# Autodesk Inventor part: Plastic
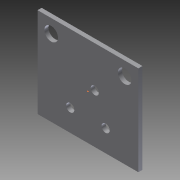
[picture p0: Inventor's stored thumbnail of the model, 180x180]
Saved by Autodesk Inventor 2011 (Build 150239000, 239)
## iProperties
Created: 2014-06
Part Number: Plastic
Document SubType Name: Modeling
Designer: Evgeny
Density: 1 g/cm^3
Author: Evgeny
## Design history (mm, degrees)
sketch "Эскиз1"
  geometry: 1 further point
sketch "Эскиз2"
  geometry: L1 (-18.5, -16.5)-(18.5, -16.5); L2 (18.5, -16.5)-(18.5, 16.5); L3 (18.5, 16.5)-(-18.5, 16.5); L4 (-18.5, 16.5)-(-18.5, -16.5); C1 r 2.5 at (-13.5, 11.5); C2 r 2.5 at (13.5, 11.5); C3 r 1.5 at (-2.5, 1.5); C4 r 1.5 at (-6.5, -8.5); C5 r 1.5 at (6.5, -8.5); 1 further point
  constraints: 8 end point, 5 centre point, 2 parallel, 1 horizontal, 1 perpendicular
  dimensions: "d0" = 37 distance between parallel lines of L2 L4; "d1" = 33 distance between parallel lines of L1 L3; "d2" = 18.5 distance from line of L4 point (0, 0); "d3" = 16.5 distance from line of L1 point (0, 0); "d4" = 5 diameter of C1; "d5" = 5 diameter of C2; "d6" = 27 distance of C2.centre C1.centre; "d7" = 13.5 horizontal distance of C1.centre point (0, 0); "d8" = 5 distance from line of C1.centre L3; "d9" = 3 diameter of C3; "d10" = 3 diameter of C4; "d11" = 3 diameter of C5; "d12" = 13 distance of C4.centre C5.centre; "d13" = 6.5 horizontal distance of point (0, 0) C4.centre; "d14" = 25 distance from line of L3 C4.centre; "d15" = 25 distance from line of L3 C5.centre; "d16" = 16 distance from line of L4 C3.centre; "d17" = 15 distance from line of L3 C3.centre
extrude "Выдавливание1" new body sketch "Эскиз2" distance "d18" = 1.5; taper "d19" = 0 deg
node "Твердое тело1"
